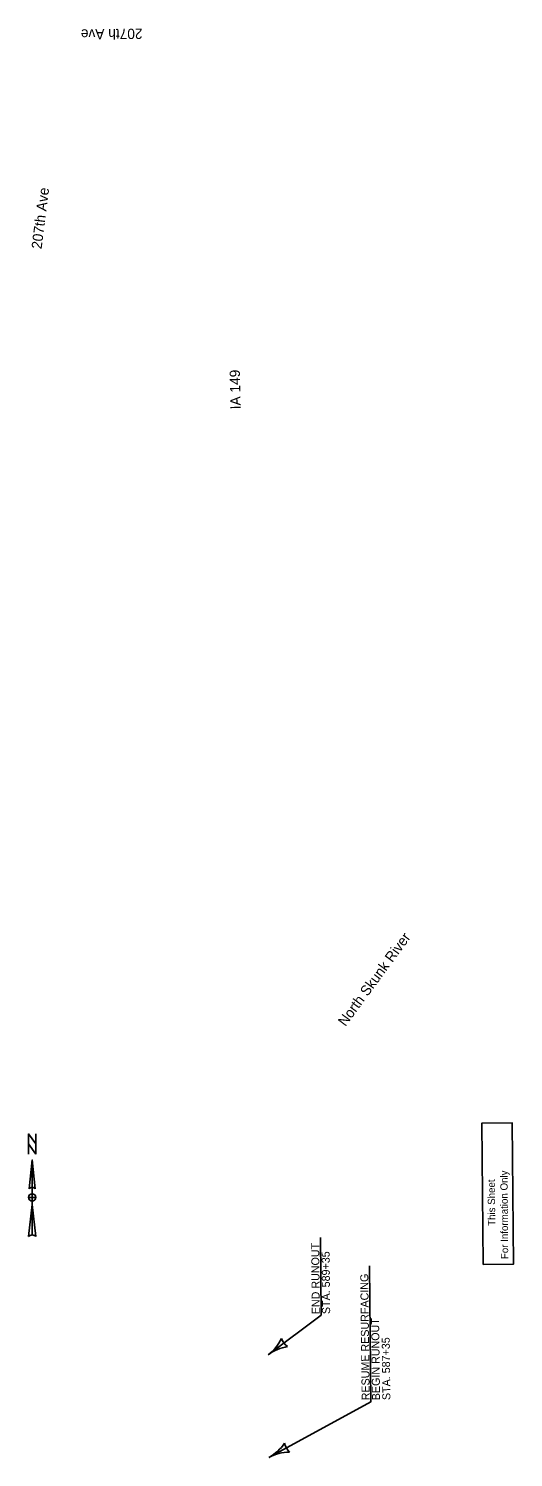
# Model space of a CAD drawing. Extents: x 23417754 to 23421386, y 6737896 to 6790956.
# Drawn here: x 23420384 to 23421330, y 6784305 to 6787091 of the extents above; entities that cross this region are included whole.
import ezdxf

# ---------------------------------------------------------------- set-up
doc = ezdxf.new("R2010")
doc.units = 0
for name, color, linetype in [('Curb', 7, 'Continuous'), ('Default', 7, 'Continuous'), ('dsnCellElements', 7, 'Continuous'), ('RasterAttachment', 7, 'Continuous')]:
    doc.layers.add(name, color=color, linetype=linetype)

msp = doc.modelspace()

# ---------------------------------------------------------------- linework, layer by layer
at = {"layer": 'Curb'}
for p, q in [((23420390.9, 6784885.3), (23420396.5, 6784829)), ((23420390.9, 6784885.3), (23420390.9, 6784738.8)), ((23420385.2, 6784829), (23420385.2, 6784829)), ((23420385.4, 6784829.5), (23420386.5, 6784830.7)), ((23420383.8, 6784736), (23420390.9, 6784798)), ((23420390.9, 6784805), (23420390.9, 6784805))]:
    msp.add_line(p, q, dxfattribs=at)
for points in [[(23421270.8, 6784681.3), (23421268.5, 6784956.9), (23421327.6, 6784957.4), (23421329.9, 6784681.8)], [(23421329.9, 6784681.8), (23421327.6, 6784957.4), (23421268.5, 6784956.9), (23421270.8, 6784681.3)], [(23420397.9, 6784896.6), (23420383.8, 6784916.3), (23420383.8, 6784936), (23420397.9, 6784916.3)]]:
    msp.add_lwpolyline(points, close=True, dxfattribs=at)
for points in [[(23420383.8, 6784896.6), (23420383.8, 6784936), (23420397.9, 6784916.3), (23420397.9, 6784936)], [(23420385.2, 6784829), (23420390.9, 6784885.3), (23420390.9, 6784831.8)], [(23420397.9, 6784812.1), (23420390.9, 6784812.1), (23420390.9, 6784819.1)], [(23420390.9, 6784805), (23420390.9, 6784812.1), (23420383.8, 6784812.1)], [(23420390.9, 6784738.8), (23420390.9, 6784798), (23420397.9, 6784736)]]:
    msp.add_lwpolyline(points, dxfattribs=at)
for centre, radius, start, end in [((23420390.9, 6784812.1), 7.04, 90, 180), ((23420390.9, 6784824.7), 7.04, 90.0204, 143.1257), ((23420390.9, 6784824.7), 7.04, 36.8481, 90.0218), ((23420390.9, 6784812.1), 7.04, 0, 90), ((23420390.9, 6784812.1), 7.04, 180, 270), ((23420390.9, 6784812.1), 7.04, 270, 360), ((23420390.9, 6784728.6), 10.2, 89.9894, 133.619), ((23420390.9, 6784728.6), 10.2, 46.4021, 90.0006)]:
    msp.add_arc(centre, radius, start, end, dxfattribs=at)
at = {"layer": 'dsnCellElements'}
for points in [[(23420851.3, 6784505.1), (23420954.5, 6784582.6), (23420953.3, 6784733.7)], [(23420852.9, 6784305.1), (23421051.6, 6784413.3), (23421048.9, 6784678.7)]]:
    msp.add_lwpolyline(points, dxfattribs=at)
for centre, radius, start, end in [((23420800.2, 6784573.1), 85, 306.9057, 334.9782), ((23420908.3, 6784547.9), 32.8, 199.1724, 234.6391), ((23420902.4, 6784437.1), 85, 98.8332, 126.9057), ((23420812.3, 6784379.8), 85, 298.5891, 326.6616), ((23420893.6, 6784230.4), 85, 90.5166, 118.5891), ((23420915.6, 6784339.2), 32.8, 190.8557, 226.3224)]:
    msp.add_arc(centre, radius, start, end, dxfattribs=at)

# ---------------------------------------------------------------- texts
at = {"layer": 'Curb'}
for s, height, p in [('This Sheet', 14.17, (23421294.4, 6784756.6)), ('For Information Only', 14.174, (23421319.7, 6784691.8))]:
    msp.add_text(s, height=height, rotation=90.4739, dxfattribs=at).set_placement(p)
at = {"layer": 'Default'}
msp.add_text('IA 149', height=20, rotation=91.1953, dxfattribs=at).set_placement((23420797.7, 6786348.8))
at = {"layer": 'dsnCellElements'}
for s, height, rotation, p in [('END RUNOUT', 15.6, 90.4726, (23420952, 6784584.4)), ('STA. 589+35', 15.605, 90.4726, (23420972.2, 6784584.6)), ('RESUME RESURFACING', 15.605, 90.6603, (23421049.4, 6784416.5)), ('BEGIN RUNOUT', 15.605, 90.6603, (23421069.6, 6784416.7)), ('STA. 587+35', 15.605, 90.6603, (23421089.8, 6784417))]:
    msp.add_text(s, height=height, rotation=rotation, dxfattribs=at).set_placement(p)
at = {"layer": 'RasterAttachment'}
for s, rotation, p in [('207th Ave', 180.7026, (23420606.1, 6787091)), ('207th Ave', 82.9289, (23420409.2, 6786660.3)), ('North Skunk River', 53.7334, (23421002, 6785144.2))]:
    msp.add_text(s, height=20, rotation=rotation, dxfattribs=at).set_placement(p)

doc.saveas('drawing.dxf')
